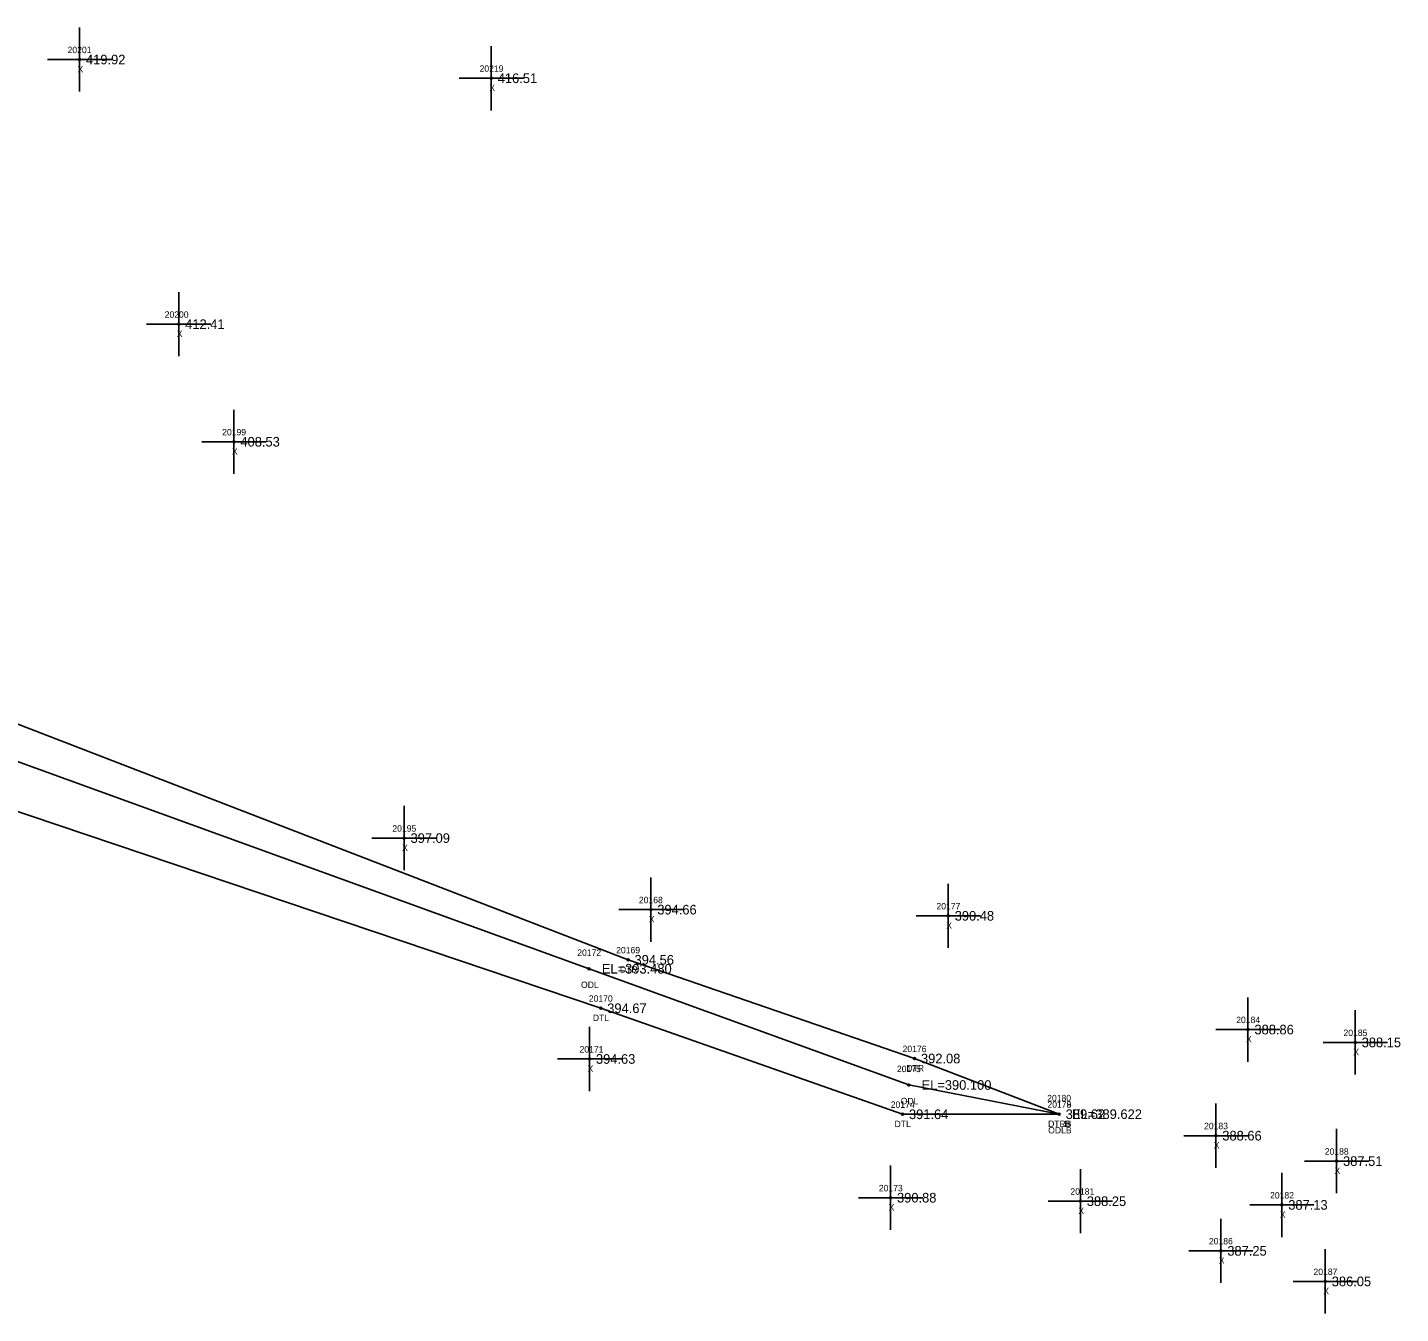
# Model space of a CAD drawing. Extents: x 2116373 to 2118139, y 979529 to 981026.
# Drawn here: x 2117006.3 to 2117220.1, y 979568.3 to 979768.5 of the extents above; entities that cross this region are included whole.
import ezdxf

# ---------------------------------------------------------------- set-up
doc = ezdxf.new("R2010")
doc.units = 0
for name, color, linetype in [('RD_EX_H2O', 7, 'Continuous'), ('RD_EX_H2O_txCode', 7, 'Continuous'), ('RD_EX_Misc', 7, 'Continuous'), ('RD_EX_Misc_txCode', 7, 'Continuous'), ('RD_EX_TX_H2O_ELEV', 7, 'Continuous'), ('RD_EX_TX_Misc_ELEV', 7, 'Continuous'), ('RD_SMD_Locator', 7, 'Continuous')]:
    doc.layers.add(name, color=color, linetype=linetype)

msp = doc.modelspace()

# ---------------------------------------------------------------- linework, layer by layer
at = {"layer": 'RD_EX_H2O'}
for points in [[(2116797.55, 979688.83), (2116805.41, 979681.75), (2116825.86, 979686.44), (2116876.74, 979692.87), (2116930.48, 979678.1), (2116996.33, 979663.31), (2117099.87, 979623.34), (2117144.47, 979607.97), (2117167, 979599.31)], [(2116419.35, 979615.24), (2116471.51, 979627.15), (2116524.74, 979637.29), (2116564.01, 979643.4), (2116629.25, 979631.55), (2116678.97, 979635.46), (2116738.46, 979663.21), (2116776.82, 979674.03), (2116792.52, 979682.03), (2116799, 979683.75), (2116807.27, 979675.26), (2116829.37, 979675.94), (2116879.68, 979679.78), (2116933.5, 979668.89), (2116988.71, 979660.02), (2117093.78, 979621.95), (2117143.56, 979603.85), (2117167, 979599.31)], [(2116808.73, 979670.75), (2116831.02, 979669.86), (2116880.96, 979672.84), (2116934.58, 979665.58), (2116984.47, 979653.27), (2117095.62, 979615.8), (2117142.6, 979599.29), (2117167, 979599.31)]]:
    msp.add_lwpolyline(points, dxfattribs=at)
at = {"layer": 'RD_EX_Misc'}
for p, q in [((2117014.46, 979758.5), (2117014.46, 979768.5)), ((2117078.57, 979755.59), (2117078.57, 979765.59)), ((2117009.46, 979763.5), (2117019.46, 979763.5)), ((2117073.57, 979760.59), (2117083.57, 979760.59)), ((2117029.9, 979717.3), (2117029.9, 979727.3)), ((2117024.9, 979722.3), (2117034.9, 979722.3)), ((2117038.5, 979698.99), (2117038.5, 979708.99)), ((2117033.5, 979703.99), (2117043.5, 979703.99)), ((2117064.99, 979637.29), (2117064.99, 979647.29)), ((2117059.99, 979642.29), (2117069.99, 979642.29)), ((2117103.41, 979626.15), (2117103.41, 979636.15)), ((2117149.72, 979625.19), (2117149.72, 979635.19)), ((2117098.41, 979631.15), (2117108.41, 979631.15)), ((2117144.72, 979630.19), (2117154.72, 979630.19)), ((2117196.39, 979607.48), (2117196.39, 979617.48)), ((2117213.09, 979605.48), (2117213.09, 979615.48)), ((2117093.86, 979602.9), (2117093.86, 979612.9)), ((2117191.39, 979612.48), (2117201.39, 979612.48)), ((2117208.09, 979610.48), (2117218.09, 979610.48)), ((2117088.86, 979607.9), (2117098.86, 979607.9)), ((2117191.39, 979590.96), (2117191.39, 979600.96)), ((2117186.39, 979595.96), (2117196.39, 979595.96)), ((2117210.19, 979587), (2117210.19, 979597)), ((2117140.74, 979581.3), (2117140.74, 979591.3)), ((2117205.19, 979592), (2117215.19, 979592)), ((2117170.29, 979580.76), (2117170.29, 979590.76)), ((2117201.66, 979580.18), (2117201.66, 979590.18)), ((2117135.74, 979586.3), (2117145.74, 979586.3)), ((2117165.29, 979585.76), (2117175.29, 979585.76)), ((2117196.66, 979585.18), (2117206.66, 979585.18)), ((2117192.17, 979573.03), (2117192.17, 979583.03)), ((2117187.17, 979578.03), (2117197.17, 979578.03)), ((2117208.43, 979568.27), (2117208.43, 979578.27)), ((2117203.43, 979573.27), (2117213.43, 979573.27))]:
    msp.add_line(p, q, dxfattribs=at)
at = {"layer": 'RD_SMD_Locator'}
for centre in [(2117014.46, 979763.5), (2117078.57, 979760.59), (2117029.9, 979722.3), (2117038.5, 979703.99), (2117064.99, 979642.29), (2117103.41, 979631.15), (2117149.72, 979630.19), (2117099.87, 979623.34), (2117093.78, 979621.95), (2117095.62, 979615.8), (2117196.39, 979612.48), (2117213.09, 979610.48), (2117093.86, 979607.9), (2117144.47, 979607.97), (2117143.56, 979603.85), (2117142.6, 979599.29), (2117167, 979599.31), (2117167, 979599.31), (2117167, 979599.31), (2117191.39, 979595.96), (2117210.19, 979592), (2117140.74, 979586.3), (2117170.29, 979585.76), (2117201.66, 979585.18), (2117192.17, 979578.03), (2117208.43, 979573.27)]:
    msp.add_circle(centre, 0.15, dxfattribs=at)

# ---------------------------------------------------------------- texts
at = {"layer": 'RD_EX_H2O_txCode'}
for s, p in [('20172', (2117091.95, 979623.95)), ('20169', (2117098.01, 979624.34)), ('DTR', (2117098.6, 979621.34)), ('ODL', (2117092.54, 979618.95)), ('20170', (2117093.75, 979616.8)), ('DTL', (2117094.38, 979613.8)), ('20176', (2117142.61, 979608.97)), ('20175', (2117141.73, 979605.85)), ('DTR', (2117143.2, 979605.97)), ('20180', (2117165.12, 979601.31)), ('20174', (2117140.77, 979600.29)), ('ODL', (2117142.32, 979600.85)), ('20178', (2117165.16, 979600.31)), ('20179', (2117165.16, 979600.31)), ('DTL', (2117141.36, 979597.29)), ('DTRB', (2117165.26, 979597.31)), ('DTLB', (2117165.28, 979597.31)), ('ODLB', (2117165.28, 979596.31))]:
    msp.add_text(s, height=1, dxfattribs=at).set_placement(p)
at = {"layer": 'RD_EX_Misc_txCode'}
for s, p in [('20201', (2117012.59, 979764.5)), ('X', (2117014.14, 979761.5)), ('20219', (2117076.74, 979761.59)), ('X', (2117078.26, 979758.59)), ('20200', (2117027.71, 979723.3)), ('X', (2117029.59, 979720.3)), ('20199', (2117036.66, 979704.99)), ('X', (2117038.18, 979701.99)), ('20195', (2117063.16, 979643.29)), ('X', (2117064.68, 979640.29)), ('20168', (2117101.55, 979632.15)), ('20177', (2117147.88, 979631.19)), ('X', (2117103.09, 979629.15)), ('X', (2117149.4, 979628.19)), ('20184', (2117194.56, 979613.48)), ('X', (2117196.08, 979610.48)), ('20185', (2117211.26, 979611.48)), ('20171', (2117092.31, 979608.9)), ('X', (2117212.78, 979608.48)), ('X', (2117093.55, 979605.9)), ('20183', (2117189.55, 979596.96)), ('X', (2117191.07, 979593.96)), ('20188', (2117208.35, 979593)), ('X', (2117209.87, 979590)), ('20173', (2117138.91, 979587.3)), ('20181', (2117168.74, 979586.76)), ('20182', (2117199.83, 979586.18)), ('X', (2117140.43, 979584.3)), ('X', (2117169.98, 979583.76)), ('X', (2117201.35, 979583.18)), ('20186', (2117190.31, 979579.03)), ('X', (2117191.85, 979576.03)), ('20187', (2117206.59, 979574.27)), ('X', (2117208.11, 979571.27))]:
    msp.add_text(s, height=1, dxfattribs=at).set_placement(p)
at = {"layer": 'RD_EX_TX_H2O_ELEV'}
for s, p in [('394.56', (2117100.87, 979622.59)), ('EL=393.480', (2117095.78, 979621.2)), ('394.67', (2117096.62, 979615.05)), ('392.08', (2117145.47, 979607.22)), ('EL=390.100', (2117145.56, 979603.1)), ('391.64', (2117143.6, 979598.54)), ('389.62', (2117168, 979598.56)), ('389.62', (2117168, 979598.56)), ('EL=389.622', (2117169, 979598.56))]:
    msp.add_text(s, height=1.5, dxfattribs=at).set_placement(p)
at = {"layer": 'RD_EX_TX_Misc_ELEV'}
for s, p in [('419.92', (2117015.46, 979762.75)), ('416.51', (2117079.57, 979759.84)), ('412.41', (2117030.9, 979721.55)), ('408.53', (2117039.5, 979703.24)), ('397.09', (2117065.99, 979641.54)), ('394.66', (2117104.41, 979630.4)), ('390.48', (2117150.72, 979629.44)), ('388.86', (2117197.39, 979611.73)), ('388.15', (2117214.09, 979609.73)), ('394.63', (2117094.86, 979607.15)), ('388.66', (2117192.39, 979595.21)), ('387.51', (2117211.19, 979591.25)), ('390.88', (2117141.74, 979585.55)), ('388.25', (2117171.29, 979585.01)), ('387.13', (2117202.66, 979584.43)), ('387.25', (2117193.17, 979577.28)), ('386.05', (2117209.43, 979572.52))]:
    msp.add_text(s, height=1.5, dxfattribs=at).set_placement(p)

doc.saveas('drawing.dxf')
